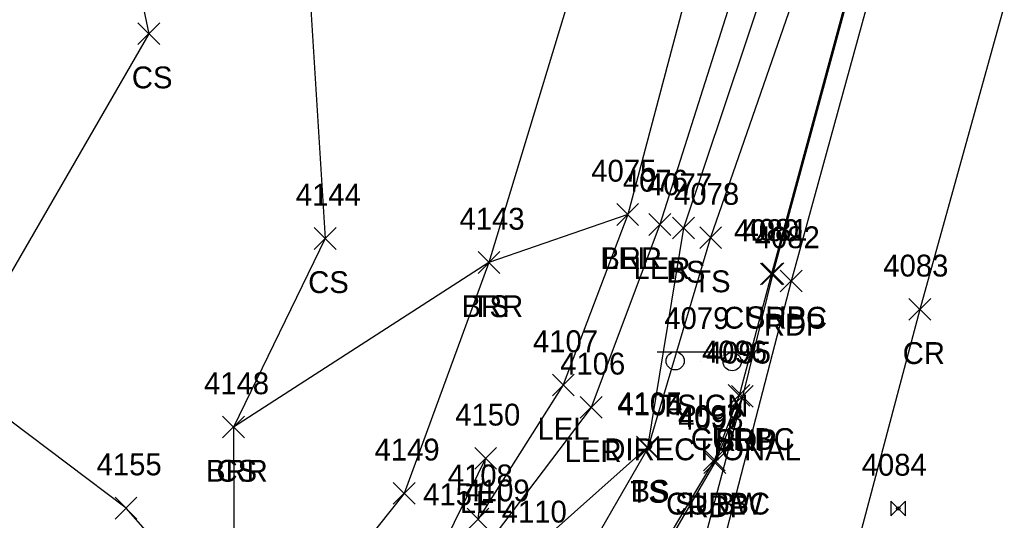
# Model space of a CAD drawing. Extents: x 1462089 to 1464015, y 730534 to 736144.
# Drawn here: x 1462678.7 to 1462768.3, y 731987.9 to 732033.7 of the extents above; entities that cross this region are included whole.
import ezdxf

# ---------------------------------------------------------------- set-up
doc = ezdxf.new("R2010")
doc.units = 0
for name, color, linetype in [('L_A', 7, 'Continuous'), ('L_I', 7, 'Continuous'), ('L_TIC', 7, 'Continuous'), ('LABL', 7, 'Continuous'), ('LARO', 7, 'Continuous'), ('LELB', 7, 'Continuous'), ('P_A', 7, 'Continuous'), ('P_I', 7, 'Continuous'), ('P_TIC', 7, 'Continuous'), ('PET', 7, 'Continuous'), ('PRC', 7, 'Continuous'), ('PSP', 7, 'Continuous'), ('R_A', 7, 'Continuous'), ('R_I', 7, 'Continuous'), ('R_TIC', 7, 'Continuous'), ('RC', 7, 'Continuous'), ('S_A', 7, 'Continuous'), ('S_C', 7, 'Continuous'), ('S_I', 7, 'Continuous'), ('SSGN', 7, 'Continuous'), ('U_A', 7, 'Continuous'), ('U_I', 7, 'Continuous'), ('U_TIC', 7, 'Continuous'), ('UWV', 7, 'Continuous')]:
    doc.layers.add(name, color=color, linetype=linetype)

msp = doc.modelspace()

# ---------------------------------------------------------------- linework, layer by layer
at = {"layer": 'L_TIC'}
for points in [[(1462689.564, 732031.443), (1462691.564, 732033.443)], [(1462691.564, 732031.443), (1462689.564, 732033.443)], [(1462733.355, 732014.91), (1462735.355, 732016.91)], [(1462735.355, 732014.91), (1462733.355, 732016.91)], [(1462733.355, 732014.91), (1462735.355, 732016.91)], [(1462735.355, 732014.91), (1462733.355, 732016.91)], [(1462736.3, 732013.995), (1462738.3, 732015.995)], [(1462738.3, 732013.995), (1462736.3, 732015.995)], [(1462738.453, 732013.67), (1462740.453, 732015.67)], [(1462740.453, 732013.67), (1462738.453, 732015.67)], [(1462705.69, 732012.718), (1462707.69, 732014.718)], [(1462707.69, 732012.718), (1462705.69, 732014.718)], [(1462740.934, 732012.793), (1462742.934, 732014.793)], [(1462742.934, 732012.793), (1462740.934, 732014.793)], [(1462720.662, 732010.517), (1462722.662, 732012.517)], [(1462722.662, 732010.517), (1462720.662, 732012.517)], [(1462720.662, 732010.517), (1462722.662, 732012.517)], [(1462722.662, 732010.517), (1462720.662, 732012.517)], [(1462727.463, 731999.313), (1462729.463, 732001.313)], [(1462729.463, 731999.313), (1462727.463, 732001.313)], [(1462730.005, 731997.266), (1462732.005, 731999.266)], [(1462732.005, 731997.266), (1462730.005, 731999.266)], [(1462697.298, 731995.467), (1462699.298, 731997.467)], [(1462699.298, 731995.467), (1462697.298, 731997.467)], [(1462697.298, 731995.467), (1462699.298, 731997.467)], [(1462699.298, 731995.467), (1462697.298, 731997.467)], [(1462735.167, 731993.631), (1462737.167, 731995.631)], [(1462737.167, 731993.631), (1462735.167, 731995.631)], [(1462735.192, 731993.536), (1462737.192, 731995.536)], [(1462737.192, 731993.536), (1462735.192, 731995.536)], [(1462720.358, 731992.602), (1462722.358, 731994.602)], [(1462722.358, 731992.602), (1462720.358, 731994.602)], [(1462712.905, 731989.403), (1462714.905, 731991.403)], [(1462714.905, 731989.403), (1462712.905, 731991.403)], [(1462687.474, 731988.051), (1462689.474, 731990.051)], [(1462689.474, 731988.051), (1462687.474, 731990.051)], [(1462719.667, 731987.04), (1462721.667, 731989.04)], [(1462721.667, 731987.04), (1462719.667, 731989.04)]]:
    msp.add_lwpolyline(points, dxfattribs=at)
at = {"layer": 'LABL'}
msp.add_lwpolyline([(1462734.355, 732015.91), (1462721.662, 732011.517), (1462698.298, 731996.467)], dxfattribs=at)
at = {"layer": 'LARO'}
for points in [[(1462811.688, 732286.33), (1462807.231, 732269.206), (1462800.04, 732238.796), (1462789.664, 732200.768), (1462786.156, 732191.387), (1462773.169, 732142.549), (1462762.591, 732101.234), (1462750.3, 732056.005), (1462737.3, 732014.995), (1462731.005, 731998.266), (1462722.217, 731986.668), (1462712.536, 731977.489), (1462705.636, 731972.393), (1462692.983, 731969.554), (1462682.236, 731971.771), (1462644.49, 731992.53), (1462610.271, 732008.803), (1462590.696, 732019.884), (1462573.649, 732029.769), (1462532.929, 732051.274)], [(1462767.804, 732143.807), (1462756.826, 732114.207), (1462759.555, 732103.744), (1462745.55, 732058.088), (1462734.355, 732015.91), (1462728.463, 732000.313), (1462720.667, 731988.04), (1462721.358, 731993.602), (1462717.768, 731986.314), (1462707.847, 731982.774), (1462698.398, 731977.755), (1462688.794, 731976.685), (1462684.49, 731979.503), (1462671.458, 731993.687), (1462653.991, 731994.715), (1462632.769, 732009.621), (1462612.672, 732017.519), (1462593.15, 732025.34), (1462587.269, 732030.624), (1462569.099, 732036.191), (1462542.763, 732056.52), (1462532.961, 732056.976)]]:
    msp.add_lwpolyline(points, dxfattribs=at)
at = {"layer": 'LELB'}
for points in [[(1462595.719, 732406.275), (1462619.401, 732406.702), (1462642.473, 732399.162), (1462667.341, 732396.485), (1462684.097, 732390.502), (1462719.426, 732377.698), (1462729.065, 732369.988), (1462742.491, 732352.09), (1462751.144, 732333.71), (1462745.112, 732312.385), (1462751.495, 732301.006), (1462756.597, 732270.551), (1462749.082, 732236.304), (1462739.504, 732197.273), (1462722.631, 732167.04), (1462705.196, 732121.694), (1462689.779, 732084.321), (1462690.843, 732066.263), (1462684.58, 732060.843), (1462690.564, 732032.443), (1462672.45, 732001.12)], [(1462811.595, 732269.296), (1462803.535, 732238.163), (1462791.508, 732188.404), (1462778.268, 732141), (1462768.169, 732099.997), (1462755.703, 732053.529), (1462741.934, 732013.793), (1462736.192, 731994.536), (1462729.099, 731982.21), (1462724.095, 731974.328), (1462718.346, 731969.418), (1462708.441, 731965.384), (1462694.104, 731962.019), (1462681.516, 731966.676), (1462670.39, 731971.8), (1462640.524, 731985.679), (1462606.108, 732003.485), (1462571.899, 732022.036), (1462531.1, 732045.758)], [(1462809.03, 732269.422), (1462801.933, 732239.135), (1462789.095, 732190.308), (1462775.293, 732141.675), (1462764.637, 732100.961), (1462752.798, 732054.523), (1462739.453, 732014.67), (1462736.167, 731994.631), (1462725.045, 731984.73), (1462716.416, 731972.55), (1462714.309, 731971.444), (1462707.004, 731968.073), (1462693.669, 731964.394), (1462682.542, 731969.027), (1462671.275, 731974.628), (1462642.39, 731988.79), (1462608.323, 732006.267), (1462574.671, 732024.465), (1462532.577, 732048.413)], [(1462767.14, 732265.982), (1462756.643, 732233.771), (1462750.546, 732195.534), (1462735.327, 732163.919), (1462718.245, 732117.574), (1462704.07, 732078.382), (1462702.898, 732059.56), (1462704.245, 732052.773), (1462706.69, 732013.718), (1462698.298, 731996.467), (1462698.398, 731977.755), (1462688.474, 731989.051), (1462672.45, 732001.12), (1462653.687, 732006.741), (1462640.584, 732015.139), (1462615.756, 732028.357), (1462597.064, 732039.343), (1462574.7, 732044.024), (1462549.989, 732062.335), (1462528.921, 732079.242)], [(1462793.485, 732260.93), (1462778.667, 732227.046), (1462768.651, 732190.093), (1462761.231, 732158.873), (1462752.183, 732117.989), (1462746.452, 732098.919), (1462740.894, 732072.951), (1462731.751, 732044.774), (1462721.662, 732011.517), (1462713.905, 731990.403), (1462707.847, 731982.774)]]:
    msp.add_lwpolyline(points, dxfattribs=at)
at = {"layer": 'P_TIC'}
for points in [[(1462746.621, 732009.499), (1462748.621, 732011.499)], [(1462748.621, 732009.499), (1462746.621, 732011.499)], [(1462748.31, 732008.824), (1462750.31, 732010.824)], [(1462750.31, 732008.824), (1462748.31, 732010.824)], [(1462760.068, 732006.231), (1462762.068, 732008.231)], [(1462762.068, 732006.231), (1462760.068, 732008.231)], [(1462743.84, 731998.272), (1462745.84, 732000.272)], [(1462745.84, 731998.272), (1462743.84, 732000.272)], [(1462743.84, 731998.272), (1462745.84, 732000.272)], [(1462745.84, 731998.272), (1462743.84, 732000.272)], [(1462741.327, 731992.221), (1462743.327, 731994.221)], [(1462743.327, 731992.221), (1462741.327, 731994.221)]]:
    msp.add_lwpolyline(points, dxfattribs=at)
at = {"layer": 'PET'}
for points in [[(1462974.36, 732735.003), (1462957.209, 732680.823), (1462945.362, 732643.955), (1462932.508, 732601.633), (1462920.152, 732563.109), (1462911.425, 732534.965), (1462898.015, 732492.334), (1462884.517, 732450.002), (1462822.419, 732278.6), (1462811.416, 732236.79), (1462797.46, 732186.944), (1462784.89, 732139.503), (1462773.379, 732098.59), (1462761.088, 732052.776), (1462749.31, 732009.824), (1462737.297, 731963.429), (1462717.097, 731889.531)], [(1462744.84, 731999.272), (1462742.327, 731993.221), (1462735.484, 731981.557), (1462730.636, 731976.017), (1462728.98, 731974.397), (1462721.402, 731968.234), (1462710.521, 731963.39), (1462695.094, 731960.105), (1462681.481, 731960.797), (1462668.269, 731966.222), (1462638.362, 731982.503), (1462604.109, 732001.118), (1462569.71, 732019.555), (1462528.556, 732041.641), (1462492.34, 732061.311), (1462453.183, 732082.825), (1462423.341, 732099.232), (1462387.222, 732118.935), (1462352.219, 732137.532), (1462321.662, 732153.593), (1462281.346, 732173.271)]]:
    msp.add_lwpolyline(points, dxfattribs=at)
at = {"layer": 'PRC'}
msp.add_lwpolyline([(1462985.716, 732731.928), (1462969.444, 732677.267), (1462957.486, 732641.208), (1462943.904, 732597.669), (1462931.653, 732559.608), (1462922.759, 732531.119), (1462910.18, 732489.033), (1462895.07, 732444.402), (1462885.161, 732408.132), (1462864.593, 732375.333), (1462853.42, 732347.258), (1462832.874, 732276.651), (1462823.233, 732232.908), (1462808.463, 732182.81), (1462796.537, 732136.818), (1462784.674, 732094.481), (1462773.756, 732052.904), (1462761.068, 732007.231), (1462748.947, 731961.516), (1462736.508, 731921.312)], dxfattribs=at)
at = {"layer": 'PSP'}
msp.add_lwpolyline([(1462968.734, 732736.5), (1462951.614, 732681.876), (1462940.588, 732646.438), (1462927.054, 732603.058), (1462915.133, 732564.778), (1462905.928, 732535.586), (1462892.756, 732493.151), (1462882.838, 732461.981), (1462878.844, 732452.238), (1462860.168, 732402.537), (1462855.981, 732390.471), (1462851.596, 732378.353), (1462831.733, 732320.544), (1462820.54, 732279.169), (1462809.4, 732237.242), (1462795.769, 732187.965), (1462782.91, 732140.192), (1462771.747, 732099.013), (1462759.214, 732053.145), (1462747.621, 732010.499), (1462744.84, 731999.272), (1462735.883, 731965.543), (1462724.347, 731923.615)], dxfattribs=at)
at = {"layer": 'R_TIC'}
for points in [[(1462746.496, 732009.465), (1462748.496, 732011.465)], [(1462748.496, 732009.465), (1462746.496, 732011.465)], [(1462743.537, 731998.365), (1462745.537, 732000.365)], [(1462745.537, 731998.365), (1462743.537, 732000.365)], [(1462741.276, 731992.462), (1462743.276, 731994.462)], [(1462743.276, 731992.462), (1462741.276, 731994.462)]]:
    msp.add_lwpolyline(points, dxfattribs=at)
at = {"layer": 'RC'}
msp.add_lwpolyline([(1462829.931, 732355.37), (1462830.592, 732355.491), (1462831.241, 732353.266), (1462834.244, 732341.275), (1462833.708, 732330.403), (1462831.715, 732320.543), (1462820.096, 732278.81), (1462808.97, 732237.559), (1462795.491, 732188.013), (1462782.739, 732140.325), (1462771.632, 732099.145), (1462759.129, 732053.252), (1462747.496, 732010.465), (1462744.537, 731999.365), (1462742.276, 731993.462), (1462735.209, 731981.654), (1462730.478, 731976.347), (1462728.98, 731974.397)], dxfattribs=at)
at = {"layer": 'SSGN'}
for p, q in [((1462737.032, 732003.351), (1462745.629, 732003.351)), ((1462741.054, 732002.447), (1462741.054, 732002.447))]:
    msp.add_line(p, q, dxfattribs=at)
for centre in [(1462738.693, 732002.517), (1462743.908, 732002.447)]:
    msp.add_circle(centre, 0.833, dxfattribs=at)
at = {"layer": 'U_TIC'}
for points in [[(1462741.276, 731992.462), (1462743.276, 731994.462)], [(1462743.276, 731992.462), (1462741.276, 731994.462)]]:
    msp.add_lwpolyline(points, dxfattribs=at)
at = {"layer": 'UWV'}
for p, q in [((1462758.424, 731989.684), (1462759.758, 731988.35)), ((1462759.758, 731989.684), (1462758.424, 731988.35))]:
    msp.add_line(p, q, dxfattribs=at)
for points in [[(1462758.424, 731989.684), (1462758.424, 731988.35)], [(1462759.758, 731988.35), (1462759.758, 731989.684)]]:
    msp.add_lwpolyline(points, dxfattribs=at)
msp.add_circle((1462759.091, 731989.017), 0.167, dxfattribs=at)

# ---------------------------------------------------------------- texts
at = {"layer": 'L_A'}
for s, p in [('CS', (1462689.005, 732027.443)), ('BRR', (1462731.844, 732010.91)), ('LEL', (1462731.993, 732010.91)), ('LER', (1462734.883, 732009.995)), ('BS', (1462737.894, 732009.67)), ('CS', (1462705.131, 732008.718)), ('TS', (1462740.344, 732008.793)), ('BRR', (1462719.15, 732006.517)), ('TS', (1462720.072, 732006.517)), ('LEL', (1462726.1, 731995.313)), ('LER', (1462728.587, 731993.266)), ('BRR', (1462695.786, 731991.467)), ('CS', (1462696.739, 731991.467)), ('TS', (1462734.602, 731989.536)), ('BS', (1462734.608, 731989.631)), ('LEL', (1462718.995, 731988.602))]:
    msp.add_text(s, height=2, dxfattribs=at).set_placement(p)
at = {"layer": 'L_I'}
for s, p in [('4075', (1462731.017, 732018.91)), ('4075', (1462731.017, 732018.91)), ('4076', (1462733.907, 732017.995)), ('4077', (1462736.114, 732017.67)), ('4144', (1462703.997, 732016.718)), ('4078', (1462738.596, 732016.793)), ('4143', (1462718.969, 732014.517)), ('4143', (1462718.969, 732014.517)), ('4107', (1462725.691, 732003.313)), ('4106', (1462728.178, 732001.266)), ('4148', (1462695.605, 731999.467)), ('4148', (1462695.605, 731999.467)), ('4105', (1462733.396, 731997.631)), ('4104', (1462733.421, 731997.536)), ('4150', (1462718.578, 731996.602)), ('4149', (1462711.204, 731993.403)), ('4155', (1462685.782, 731992.051)), ('4108', (1462717.896, 731991.04)), ('4151', (1462715.642, 731989.314)), ('4109', (1462719.437, 731989.668)), ('4109', (1462719.437, 731989.668)), ('4110', (1462722.833, 731987.73))]:
    msp.add_text(s, height=2, dxfattribs=at).set_placement(p)
at = {"layer": 'P_A'}
for s, p in [('SHP', (1462745.156, 732005.499)), ('RDP', (1462746.798, 732004.824)), ('CR', (1462759.501, 732002.231)), ('SHP', (1462742.375, 731994.272)), ('RDP', (1462742.328, 731994.272)), ('RDP', (1462739.816, 731988.221))]:
    msp.add_text(s, height=2, dxfattribs=at).set_placement(p)
at = {"layer": 'P_I'}
for s, p in [('4081', (1462744.849, 732013.499)), ('4082', (1462745.972, 732012.824)), ('4083', (1462757.73, 732010.231)), ('4095', (1462741.502, 732002.272)), ('4095', (1462741.502, 732002.272)), ('4098', (1462738.989, 731996.221))]:
    msp.add_text(s, height=2, dxfattribs=at).set_placement(p)
at = {"layer": 'R_A'}
for p in [(1462743.079, 732005.465), (1462740.12, 731994.365), (1462737.859, 731988.462)]:
    msp.add_text('CURBC', height=2, dxfattribs=at).set_placement(p)
at = {"layer": 'R_I'}
for s, p in [('4080', (1462744.071, 732013.465)), ('4096', (1462741.144, 732002.365)), ('4097', (1462738.937, 731996.462))]:
    msp.add_text(s, height=2, dxfattribs=at).set_placement(p)
at = {"layer": 'S_A'}
msp.add_text('TSIGN', height=2, dxfattribs=at).set_placement((1462737.23, 731997.429))
at = {"layer": 'S_C'}
msp.add_text('DIRECTIONAL', height=2, dxfattribs=at).set_placement((1462732.214, 731993.429))
at = {"layer": 'S_I'}
msp.add_text('4079', height=2, dxfattribs=at).set_placement((1462737.702, 732005.429))
at = {"layer": 'U_A'}
msp.add_text('SUBW', height=2, dxfattribs=at).set_placement((1462738.685, 731988.462))
at = {"layer": 'U_I'}
for s, p in [('4097', (1462738.937, 731996.462)), ('4084', (1462755.752, 731992.017))]:
    msp.add_text(s, height=2, dxfattribs=at).set_placement(p)

doc.saveas('drawing.dxf')
